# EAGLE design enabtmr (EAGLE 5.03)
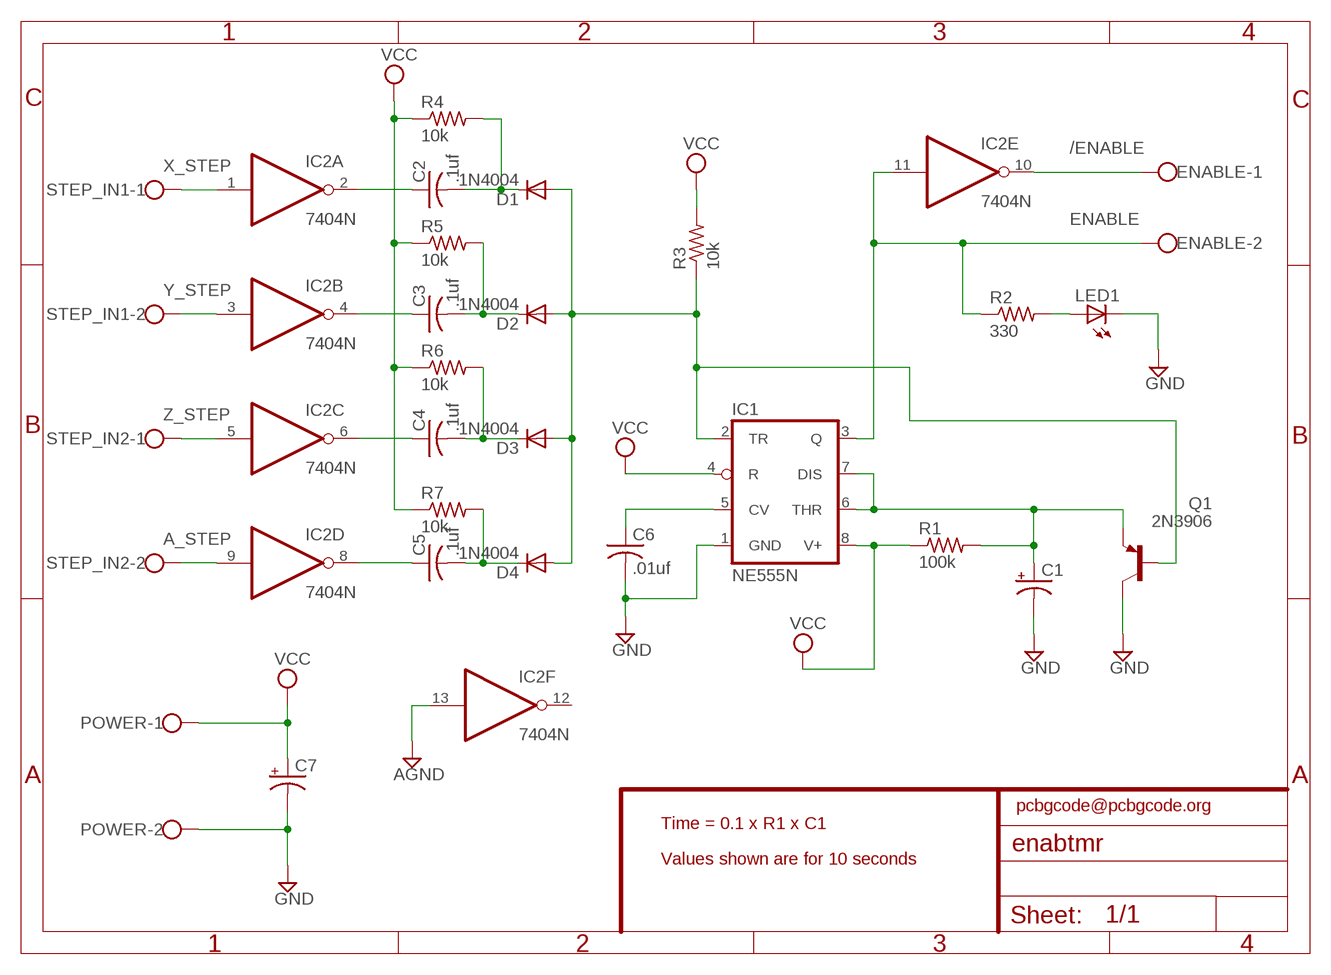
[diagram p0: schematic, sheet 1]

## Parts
C1  CPOL-USE15-5AXIAL  [E15-5]
C2  .1uf  C-US050-030X075  [C050-030X075]
C3  .1uf  C-US050-030X075  [C050-030X075]
C4  .1uf  C-US050-030X075  [C050-030X075]
C5  .1uf  C-US050-030X075  [C050-030X075]
C6  .01uf  C-US050-030X075  [C050-030X075]
C7  CPOL-USE15-5AXIAL  [E15-5]
D1  1N4004  [DO41-10]
D2  1N4004  [DO41-10]
D3  1N4004  [DO41-10]
D4  1N4004  [DO41-10]
ENABLE  W237-102  [W237-102]
IC1  NE555N  [DIL08]
IC2  7404N  [DIL14]
LED1  LED5MM  [LED5MM]
POWER  W237-102  [W237-102]
Q1  2N3906  [TO92]
R1  100k  R-US_0207/12  [0207/12]
R2  330  R-US_0207/12  [0207/12]
R3  10k  R-US_0207/12  [0207/12]
R4  10k  R-US_0207/12  [0207/12]
R5  10k  R-US_0207/12  [0207/12]
R6  10k  R-US_0207/12  [0207/12]
R7  10k  R-US_0207/12  [0207/12]
STEP_IN1  W237-102  [W237-102]
STEP_IN2  W237-102  [W237-102]

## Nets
/ENABLE: ENABLE.1 IC2.10(E:O)
A_STEP: IC2.9(D:I) STEP_IN2.2
AGND: IC2.13(F:I)
ENABLE: ENABLE.2 IC1.3(Q) IC2.11(E:I) R2.1
GND: C1.- C6.2 C7.- IC1.1(GND) LED1.K(C) POWER.2 Q1.1(C)
N$2: C6.1 IC1.5(CV)
N$3: D1.A D2.A D3.A D4.A IC1.2(TR) Q1.2(B) R3.1
N$4: C2.1 IC2.2(A:O)
N$5: C3.1 IC2.4(B:O)
N$6: C4.1 IC2.6(C:O)
N$7: C5.1 IC2.8(D:O)
N$8: C5.2 D4.C R7.2
N$9: C4.2 D3.C R6.2
N$10: C3.2 D2.C R5.2
N$11: C2.2 D1.C R4.2
N$19: LED1.A R2.2
N$20: C1.+ IC1.6(THR) IC1.7(DIS) Q1.3(E) R1.2
VCC: C7.+ IC1.4(R) IC1.8(V+) POWER.1 R1.1 R3.2 R4.1 R5.1 R6.1 R7.1
X_STEP: IC2.1(A:I) STEP_IN1.1
Y_STEP: IC2.3(B:I) STEP_IN1.2
Z_STEP: IC2.5(C:I) STEP_IN2.1
Unconnected: IC2.12(F:O)

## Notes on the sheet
- pcbgcode@pcbgcode.org
- Time = 0.1 x R1 x C1
- Values shown are for 10 seconds

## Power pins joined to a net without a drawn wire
GND: IC2.7(P:GND)
VCC: IC2.14(P:VCC)

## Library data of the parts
C1 C7 = rcl:CPOL-US: POLARIZED CAPACITOR, American symbol
C2-C6 = rcl:C-US: CAPACITOR, American symbol
D1-D4 = diode:1N4004: DIODE
ENABLE POWER STEP_IN1 STEP_IN2 = con-wago-500:W237-102: WAGO SCREW CLAMP
IC1 = linear:*555: TIMER
IC2 = 74xx-us:74*04: Hex INVERTER
LED1 = led:LED: LED
Q1 = transistor-pnp:2N3906: PNP Transistor
R1-R7 = rcl:R-US_: RESISTOR, American symbol

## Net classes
0 default: width 1.27 mm, clearance 0.508 mm

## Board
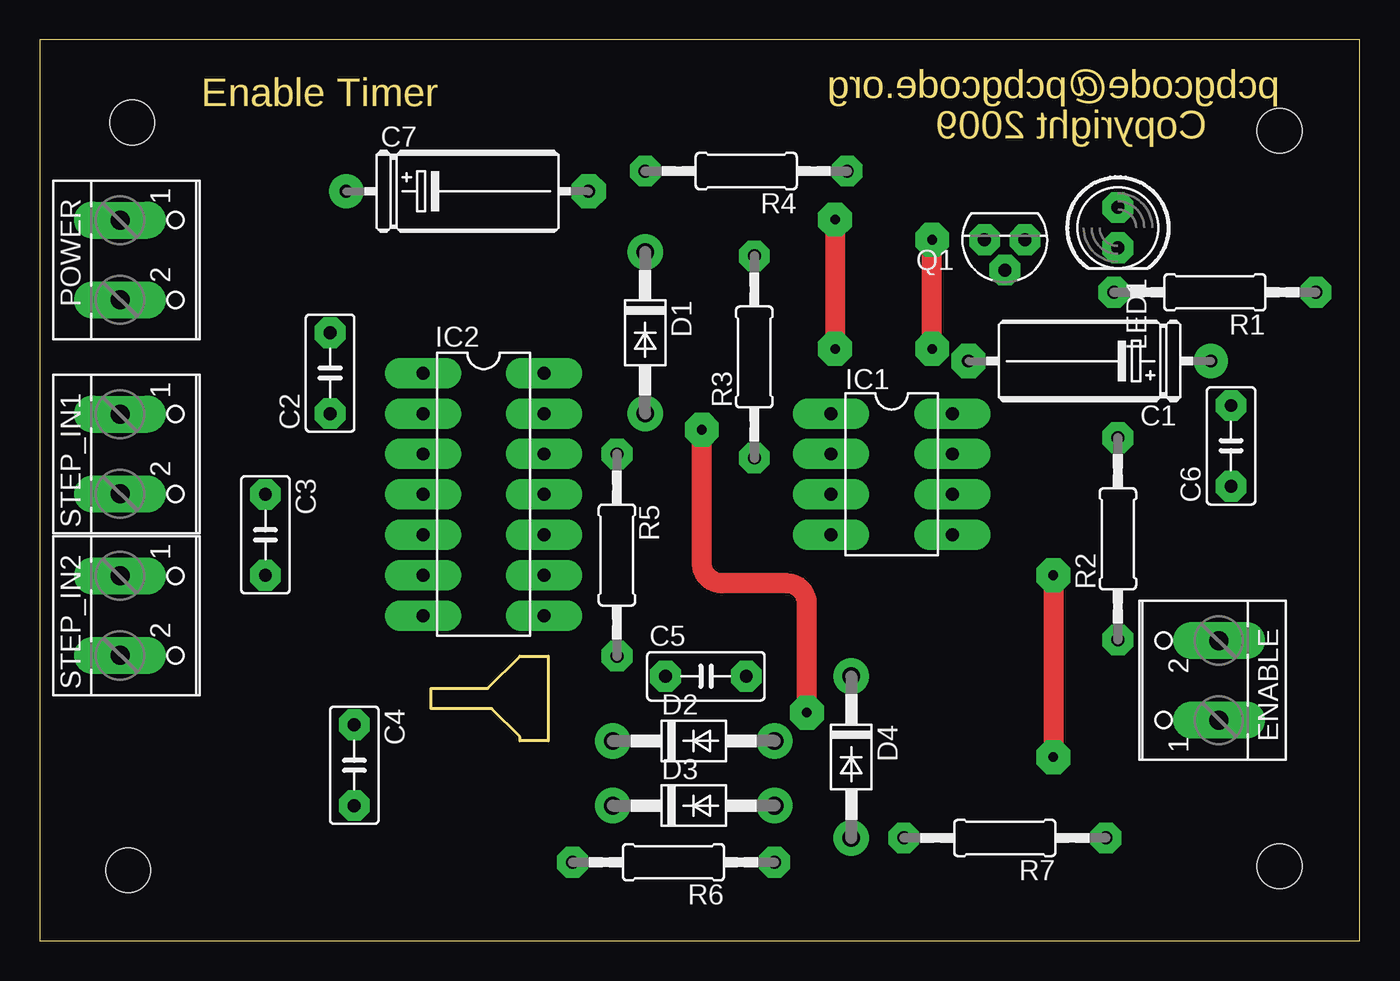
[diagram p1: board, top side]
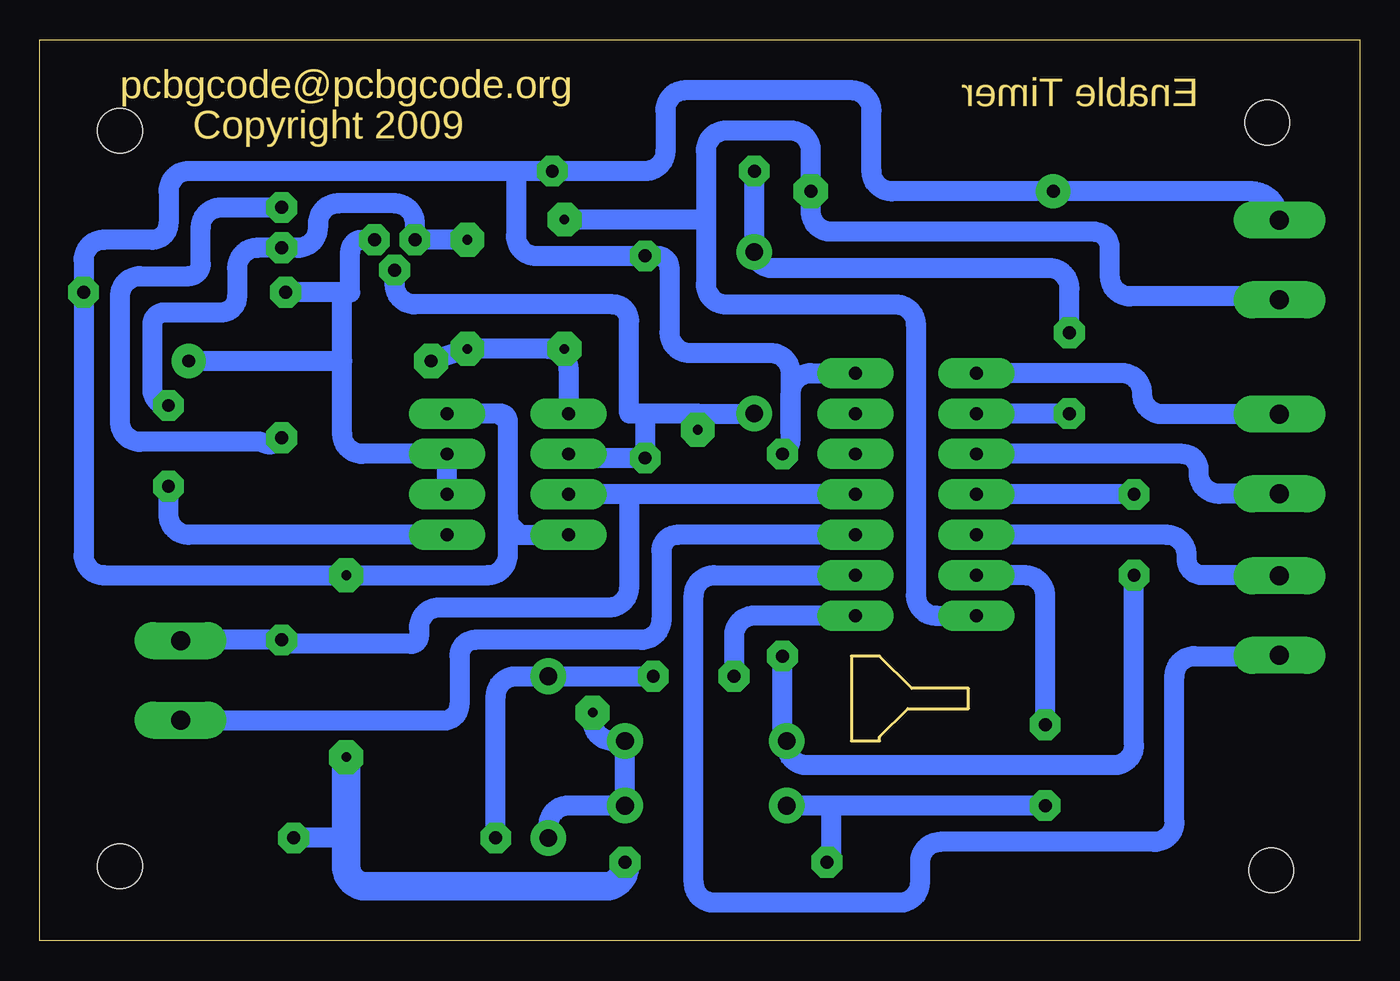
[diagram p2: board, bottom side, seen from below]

Size 82.98 x 56.63 mm. Coordinates in mm from the lower left corner, seen from the top.
Outline: 0,0 82.98,0 82.98,56.63 0,56.63 0,0
Copper layers (1*16): Top 0.035mm / dielectric 1.5mm / Bottom 0.035mm
Design rules "default": minimum track width 30mil, minimum drill 22mil, track to track 20mil, track to pad 20mil, pad to pad 10mil, via to via 8mil, smd to smd 8mil, copper to edge 40mil, drill to drill 30mil, minimum pad ring 22mil, minimum via ring 30mil, stop-mask expansion 4mil, vias tented up to drill 0mil, thermal gap 10mil
Holes 2.8 mm at 5.55,4.44 5.8,51.43 77.94,50.92 77.94,4.69
Milling: 9 lines

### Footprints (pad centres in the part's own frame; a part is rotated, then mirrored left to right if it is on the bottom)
E15-5 = drill 0.813 pad 2.159 round: + -7.62,0 | drill 0.813 pad 2.159 octagon: - 7.62,0
C050-030X075 = drill 0.813 octagon: 1 -2.54,0; 2 2.54,0
DO41-10 = drill 1.118 round: A 5.08,0; C -5.08,0
W237-102 = drill 1.194 long: 1 -2.5,-1.27; 2 2.5,-1.27
DIL08 = drill 0.813 long: 1 -3.81,-3.81; 2 -1.27,-3.81; 3 1.27,-3.81; 4 3.81,-3.81; 5 3.81,3.81; 6 1.27,3.81; 7 -1.27,3.81; 8 -3.81,3.81
DIL14 = drill 0.813 long: 1 -7.62,-3.81; 2 -5.08,-3.81; 3 -2.54,-3.81; 4 0,-3.81; 5 2.54,-3.81; 6 5.08,-3.81; 7 7.62,-3.81; 8 7.62,3.81; 9 5.08,3.81; 10 2.54,3.81; 11 0,3.81; 12 -2.54,3.81; 13 -5.08,3.81; 14 -7.62,3.81
LED5MM = drill 0.813 octagon: A -1.27,0; K 1.27,0
TO92 = drill 0.813 octagon: 1 1.27,0; 2 0,1.905; 3 -1.27,0
0207/12 = drill 0.813 octagon: 1 -6.35,0; 2 6.35,0

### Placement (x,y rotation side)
C1  66,36.44 180 top
C2  18.25,35.68 90 top
C3  14.19,25.52 270 top
C4  19.77,11.04 270 top
C5  41.87,16.63 0 top
C6  74.89,31.11 90 top
C7  26.89,47.11 0 top
D1  38.06,38.22 270 top
D2  41.11,12.57 0 top
D3  41.11,8.5 0 top
D4  51.02,11.55 270 top
ENABLE  72.86,16.38 90 top
IC1  53.56,29.33 270 top
IC2  27.9,28.06 270 top
LED1  67.78,44.83 270 top
POWER  6.31,42.79 270 top
Q1  60.67,44.06 180 top
R1  73.88,40.76 180 top
R2  67.78,25.27 90 top
R3  44.92,36.7 90 top
R4  44.41,48.38 180 top
R5  36.28,24.25 270 top
R6  39.84,4.95 180 top
R7  60.67,6.47 180 top
STEP_IN1  6.31,30.6 270 top
STEP_IN2  6.31,20.44 270 top

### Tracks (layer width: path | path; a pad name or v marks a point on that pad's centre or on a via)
/ENABLE
  Bottom 1.27: 73.88,14.35 73.92,14.39 ENABLE.1 | ENABLE.1 74.13,14.35 | IC2.10 42.89,25.52 arc-90 43.9,24.51 43.9,20.19 arc90 45.17,18.92 55.59,18.92 arc-90 56.6,17.9 56.6,14.85 arc90 57.62,13.84 74.17,13.84 | 74.17,13.84 74.38,13.84 | 74.17,13.84 arc-90 ENABLE.1
A_STEP
  Bottom 1.27: IC2.9 40.6,22.98 arc-90 41.87,21.71 41.87,3.68 arc-90 40.6,2.41 28.92,2.41 arc-90 27.65,3.68 27.65,4.95 arc90 26.38,6.22 12.92,6.22 arc-90 11.65,7.49 11.65,16.63 arc90 10.38,17.9 5.3,17.9 arc90 5.26,17.94 STEP_IN2.2
ENABLE
  Bottom 1.27: IC2.11 45.94,28.06 | 45.94,28.06 IC1.3 | 45.94,28.06 45.94,22.22 arc90 47.21,20.95 57.87,20.95 arc-90 59.14,19.68 59.14,19.17 arc90 59.65,18.66 67.78,18.66 R2.1 74.38,18.92 arc-90 74.34,18.88 ENABLE.2
GND  (via drill 0.6)
  Top 1.27: v56.1,37.21 v56.1,44.06 | v50,45.33 v50,37.21
  Bottom 1.27: IC2.7 26.63,20.44 arc90 27.9,21.71 27.9,38.73 arc-90 29.17,40 39.84,40 arc90 41.11,41.27 41.11,45.08 | C7.- 34.51,49.4 | 41.11,45.08 41.11,45.33 49.75,45.33 arc90 v50,45.33 | 51.02,37.21 arc90 49.75,35.94 | 49.75,35.94 IC1.1 | C1.- v56.1,37.21 v50,37.21 51.02,37.21 | 51.02,37.21 arc90 49.75,35.94 | C7.- 34.51,45.84 arc-90 33.24,44.57 16.73,44.57 arc90 15.71,43.56 15.71,41.78 arc-90 14.44,40.51 5.08,40.51 arc-90 POWER.2 | C7.- 34.51,49.65 arc-90 35.78,50.92 39.84,50.92 arc-90 41.11,49.65 41.11,45.08 | C6.2 arc90 75.91,34.67 75.91,38.73 arc90 75.15,39.49 71.59,39.49 arc-90 70.57,40.51 70.57,42.29 arc90 69.3,43.56 LED1.K 66.76,43.56 arc-90 65.49,44.83 65.49,45.08 arc90 64.22,46.35 60.67,46.35 arc90 59.4,45.08 Q1.1 v56.1,44.06
N$2
  Bottom 1.27: IC1.5 73.62,25.52 arc90 74.89,26.79 C6.1
N$3  (via drill 0.6)
  Top 1.27: v48.22,14.35 48.22,21.2 arc90 46.95,22.47 42.89,22.47 arc-90 41.62,23.74 v41.62,32.13
  Bottom 1.27: 41.62,33.14 D1.A | 41.62,33.14 44.92,33.14 | 44.92,33.14 45.94,33.14 45.94,38.98 arc-90 46.95,40 59.4,40 arc90 60.67,41.27 Q1.2 | v41.62,32.13 41.62,33.14 | v48.22,14.35 48.22,13.84 arc-90 46.95,12.57 D2.A 46.44,12.31 46.19,12.06 D3.A 49.75,8.5 arc-90 51.02,7.23 D4.A | IC1.2 arc-90 49.49,30.35 R3.1 44.92,33.14
N$4
  Bottom 1.27: 24.35,33.14 IC2.2 C2.1
N$5
  Bottom 1.27: C3.1 IC2.4
N$6
  Bottom 1.27: IC2.6 21.04,22.98 arc90 19.77,21.71 C4.1
N$7
  Bottom 1.27: C5.1 39.33,19.17 arc90 38.06,20.44 IC2.8
N$8
  Bottom 1.27: C5.2 D4.C 53.05,16.63 arc-90 54.32,15.36 R7.2
N$9
  Bottom 1.27: C4.2 33.24,8.5 | 33.24,8.5 D3.C | R6.2 arc-90 33.24,5.2 33.24,8.5
N$10
  Bottom 1.27: R5.2 36.28,12.82 arc-90 D2.C 36.03,12.31 arc-90 34.76,11.04 15.46,11.04 arc-90 14.19,12.31 C3.2
N$11
  Bottom 1.27: R4.2 D1.C arc-90 36.79,42.29 19.52,42.29 arc90 18.25,41.02 C2.2
N$19
  Bottom 1.27: R2.2 arc90 69.05,31.36 76.67,31.36 arc90 77.94,32.63 77.94,40.51 arc90 76.67,41.78 73.62,41.78 arc-90 72.86,42.54 72.86,44.83 arc90 71.59,46.1 LED1.A
N$20
  Bottom 1.27: IC1.6 IC1.7 62.7,30.6 arc90 63.97,31.87 63.97,36.44 | 63.97,36.44 63.97,40.76 | 63.97,36.44 C1.+ | 63.97,40.76 R1.2 | Q1.3 62.7,44.06 arc-90 63.46,43.3 63.46,40.76 63.97,40.76
VCC  (via drill 0.6)
  Top 1.27: v63.72,22.98 v63.72,11.55
  Bottom 1.27: 50,25.27 IC1.4 52.79,25.52 53.56,26.28 53.56,26.79 | 53.56,26.79 53.56,32.63 | 53.56,32.63 54.06,33.14 | 57.62,33.14 IC1.8 54.06,33.14 | IC2.14 34.51,35.68 arc-90 35.78,34.41 35.78,31.87 | 35.78,31.87 35.78,35.68 arc-90 37.05,36.95 42.13,36.95 arc90 43.4,38.22 43.4,42.29 arc-90 44.16,43.05 R3.2 arc90 45.43,43.05 51.78,43.05 | 35.78,31.87 35.78,31.64 arc45 36.15,30.74 R5.1 | 53.05,48.38 R4.1 44.92,48.38 arc-90 43.65,49.65 43.65,52.19 arc90 42.38,53.46 31.97,53.46 arc90 30.7,52.19 30.7,48.38 | C7.+ arc-90 18.97,46.82 | C7.+ 29.43,47.11 | 29.43,47.11 arc90 30.7,48.38 | 53.05,44.32 arc-90 51.78,43.05 | 53.05,44.32 arc-90 51.78,43.05 | 53.05,48.38 53.05,44.32 | 29.43,47.11 arc90 30.7,48.38 | 54.83,22.98 arc-90 53.56,24.25 | 53.56,24.25 53.56,26.79 | 53.56,32.63 arc-90 54.06,33.14 | 53.56,24.25 53.56,32.63 | 54.83,22.98 arc-90 53.56,24.25 | 54.83,22.98 v63.72,22.98 78.96,22.98 arc90 80.23,24.25 R1.1 80.23,42.79 arc90 78.96,44.06 75.91,44.06 arc-90 74.89,45.08 74.89,47.11 arc90 73.62,48.38 53.05,48.38 | POWER.1 arc-90 6.86,47.11 C7.+ | 63.72,6.47 R7.1
  Bottom 1.778: R6.1 46.19,4.69 arc90 47.46,3.42 62.45,3.42 arc90 63.72,4.69 63.72,6.47 v63.72,11.55
X_STEP
  Bottom 1.27: STEP_IN1.1 12.41,33.1 arc90 13.68,34.37 13.68,34.41 arc-90 14.95,35.68 IC2.1
Y_STEP
  Bottom 1.27: STEP_IN1.2 8.85,28.1 arc90 10.12,29.37 10.12,29.59 arc-90 11.14,30.6 IC2.3
Z_STEP
  Bottom 1.27: IC2.5 12.15,25.52 arc90 10.88,24.25 10.88,24 arc-90 9.87,22.98 5.04,22.98 STEP_IN2.1

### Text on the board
Milling: Enable Timer | pcbgcode@pcbgcode.org | Copyright 2009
